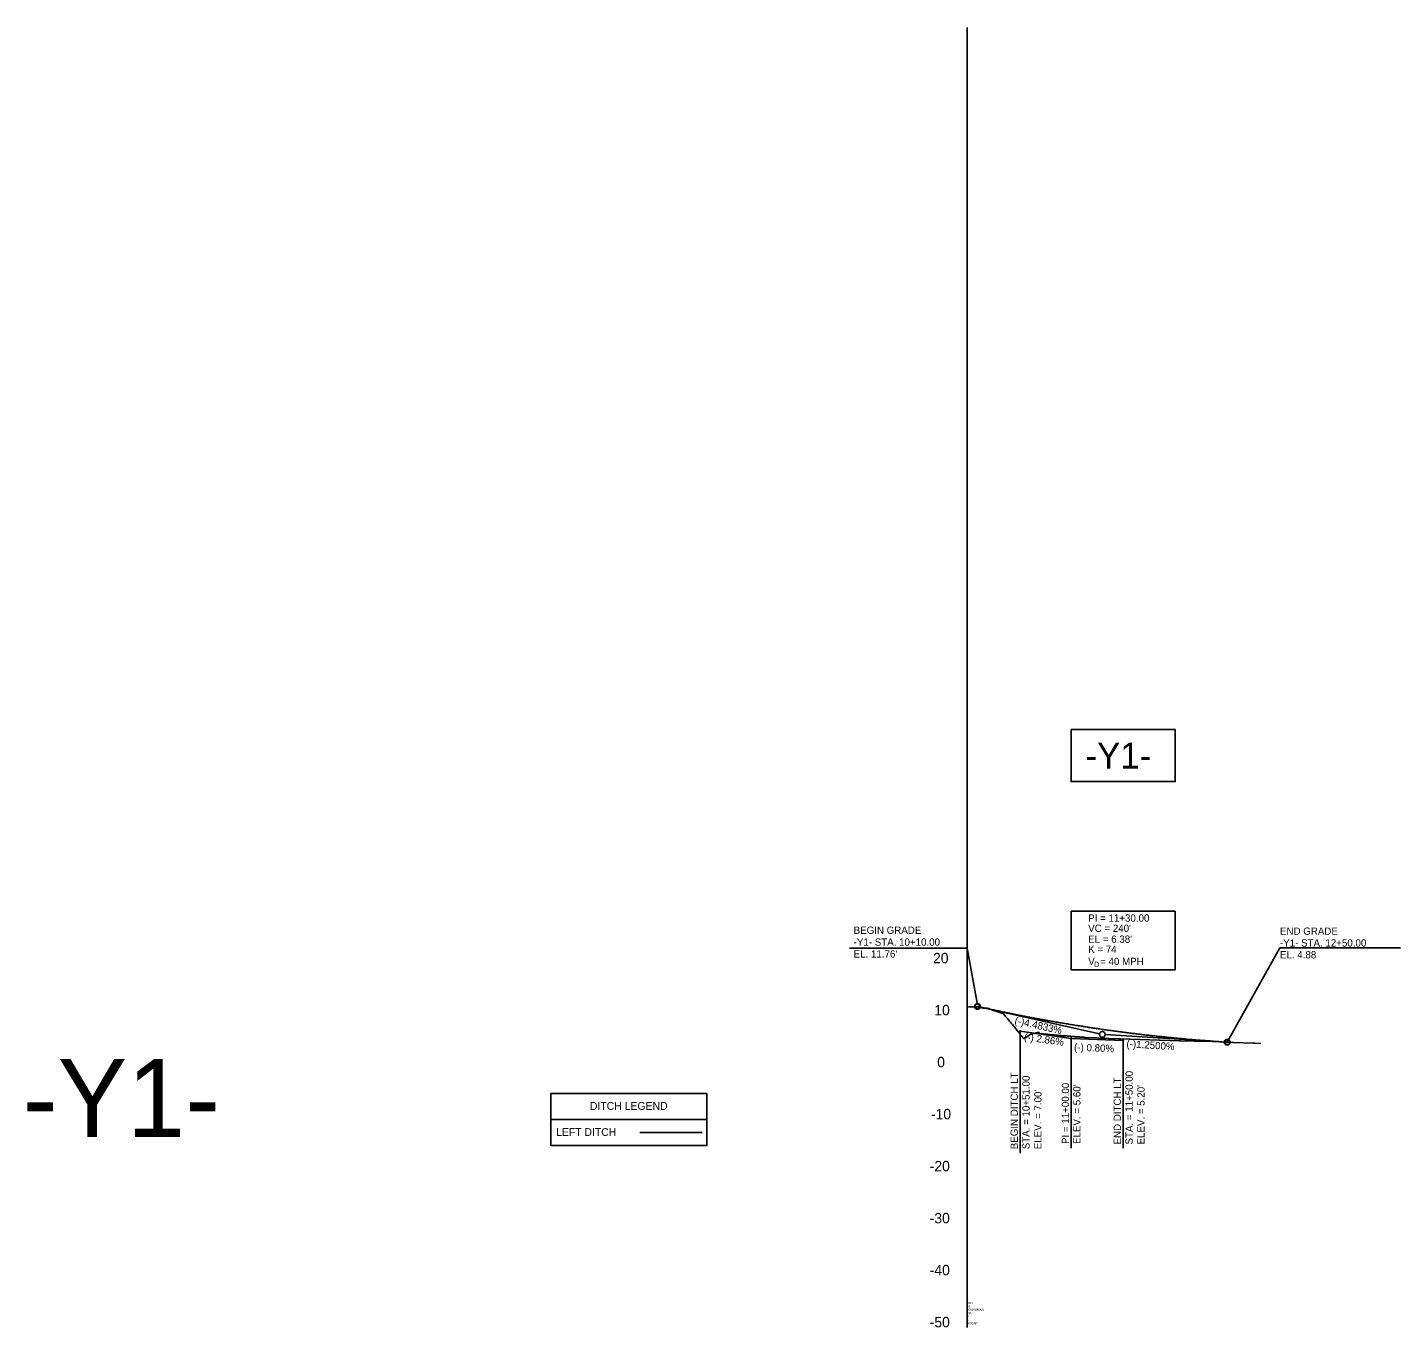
# Model space of a CAD drawing. Extents: x 1626634 to 1638383, y 876896 to 886347.
# Drawn here: x 1637064 to 1638383, y 885097 to 886347 of the extents above; entities that cross this region are included whole.
import ezdxf

# ---------------------------------------------------------------- set-up
doc = ezdxf.new("R2010")
doc.units = 0
for name, color, linetype in [('Exist Profile Cell', 7, 'Continuous'), ('Exist Vertical Profile Ground Line', 7, 'Continuous'), ('Exist Vertical Profile Vertical Axis Label', 7, 'Continuous'), ('Prop Shade Heavy', 7, 'Continuous'), ('Prop Vertical Profile Curve Label', 7, 'Continuous'), ('Prop Vertical Profile Grade', 7, 'Continuous'), ('Prop Vertical Profile Grade Label', 7, 'Continuous'), ('Prop VPI Label', 7, 'Continuous'), ('Scratch_Level_0', 7, 'Continuous'), ('Sheet Block System Information CELL', 7, 'Continuous'), ('Sheet PE Seal Cell', 7, 'Continuous'), ('Stewart Plot Border Xerox6279 and LJ5000', 7, 'Continuous')]:
    doc.layers.add(name, color=color, linetype=linetype)

msp = doc.modelspace()

# ---------------------------------------------------------------- linework, layer by layer
at = {"layer": 'Exist Profile Cell'}
msp.add_line((1637966.7, 885097.1), (1637966.7, 886347.1), dxfattribs=at)
at = {"layer": 'Exist Vertical Profile Ground Line'}
for points in [[(1637966.7, 885405.3), (1637968.7, 885405.4), (1637971.1, 885405.5), (1637972, 885405.5), (1637972.9, 885405.5), (1637973.9, 885405.5), (1637974.8, 885405.5), (1637975.7, 885405.5), (1637976.7, 885405.5), (1637977.2, 885405.5), (1637977.6, 885405.4), (1637978.5, 885405.2), (1637979.4, 885405), (1637980.4, 885404.8), (1637981.3, 885404.6), (1637982.2, 885404.4), (1637983.2, 885404.2), (1637983.5, 885404.1), (1637984.1, 885404.1), (1637985, 885404.1), (1637986, 885404.1), (1637986.9, 885404), (1637987.3, 885404), (1637987.8, 885403.8), (1637988.7, 885403.4), (1637989.7, 885403), (1637990.6, 885402.6), (1637991.7, 885402.1), (1637992.5, 885401.9), (1637993.4, 885401.6), (1637994.3, 885401.3), (1637995.3, 885401), (1637996.2, 885400.7), (1637997.1, 885400.5), (1637998.1, 885400.2), (1637999, 885399.9), (1638000.1, 885399.6), (1638000.8, 885399.5), (1638001.2, 885399.4), (1638001.8, 885398.8), (1638002.7, 885397.6), (1638003.6, 885396.4), (1638004.6, 885395.3), (1638005.5, 885394.2), (1638006.4, 885393), (1638007.4, 885391.9), (1638008.3, 885390.8), (1638009.2, 885389.8), (1638010.2, 885388.7), (1638011.1, 885387.6), (1638011.5, 885387.1), (1638012, 885386.5), (1638012.9, 885385.2), (1638013.9, 885384), (1638014.8, 885382.8), (1638015.7, 885381.6), (1638016.7, 885380.4), (1638017.6, 885379.2), (1638018.5, 885378.1), (1638019.5, 885376.9), (1638020.4, 885375.8), (1638021, 885375.1), (1638021.3, 885375.2), (1638022.2, 885375.6), (1638022.7, 885375.7), (1638023.2, 885376.1), (1638024.1, 885376.7), (1638025, 885377.4), (1638026, 885378), (1638026.9, 885378.7), (1638028.1, 885379.2), (1638028.8, 885379.4), (1638029.7, 885379.6), (1638030.6, 885379.8), (1638031.6, 885380), (1638032.5, 885380.3), (1638032.9, 885380.4), (1638033.4, 885380.5), (1638034.3, 885380.8), (1638035.4, 885381.1), (1638036.2, 885379.8), (1638037.1, 885379.7), (1638038.1, 885379.7), (1638039, 885379.6), (1638039.9, 885379.5), (1638040.9, 885379.4), (1638041.8, 885379.3), (1638042.7, 885379.2), (1638043.7, 885379.1), (1638044.6, 885379), (1638045.5, 885378.9), (1638046.4, 885378.8), (1638047.4, 885378.7), (1638048.3, 885378.7), (1638049.2, 885378.6), (1638050.2, 885378.5), (1638051.1, 885378.4), (1638052, 885378.3), (1638053, 885378.2), (1638053.9, 885378.2), (1638054.8, 885378.1)], [(1638054.8, 885378.1), (1638055.7, 885378), (1638056.7, 885377.9), (1638057.6, 885377.8), (1638058.5, 885377.8), (1638059.5, 885377.7), (1638060.4, 885377.6), (1638061.3, 885377.5), (1638062.3, 885377.5), (1638063.2, 885377.4), (1638064.1, 885377.3), (1638065.1, 885377.2), (1638066, 885377.2), (1638066.9, 885377.1), (1638067.8, 885377), (1638068.8, 885377), (1638069.7, 885376.9), (1638070.6, 885376.8), (1638070.9, 885376.8), (1638071.6, 885376.8), (1638072.1, 885376.7), (1638072.5, 885376.7), (1638073.4, 885376.6), (1638074.4, 885376.6), (1638075.3, 885376.5), (1638076.2, 885376.4), (1638077.1, 885376.4), (1638078.1, 885376.3), (1638079, 885376.3), (1638079.9, 885376.2), (1638080.9, 885376.2), (1638091.8, 885375.6), (1638093.4, 885375.5), (1638112.5, 885374.8), (1638114.3, 885374.7), (1638133.2, 885374.1), (1638151.2, 885373.5), (1638152.3, 885373.5), (1638170.5, 885372.9), (1638171.3, 885372.8), (1638171.8, 885372.8), (1638184.9, 885372.5), (1638185.4, 885372.5), (1638202.4, 885372.1), (1638203, 885372.1), (1638222.1, 885371.3), (1638222.8, 885371.3), (1638241.8, 885370.6), (1638243.3, 885370.5), (1638248.9, 885370.3)]]:
    msp.add_lwpolyline(points, dxfattribs=at)
at = {"layer": 'Prop Shade Heavy'}
for points in [[(1637566.7, 885322.1), (1637716.7, 885322.1), (1637716.7, 885297.1), (1637566.7, 885297.1)], [(1637566.7, 885297.1), (1637716.7, 885297.1), (1637716.7, 885272.1), (1637566.7, 885272.1)]]:
    msp.add_lwpolyline(points, close=True, dxfattribs=at)
at = {"layer": 'Prop Vertical Profile Curve Label'}
for centre in [(1637976.7, 885405.9), (1638216.7, 885371.5)]:
    msp.add_circle(centre, 2.25, dxfattribs=at)
at = {"layer": 'Prop Vertical Profile Grade'}
msp.add_spline([(1637976.7, 885405.9), (1637981.5, 885404.9), (1637986.3, 885403.8), (1637991.1, 885402.8), (1637995.9, 885401.8), (1638000.7, 885400.8), (1638005.5, 885399.8), (1638010.3, 885398.8), (1638015.1, 885397.8), (1638019.9, 885396.9), (1638024.7, 885396), (1638029.5, 885395), (1638034.3, 885394.1), (1638039.1, 885393.3), (1638043.9, 885392.4), (1638048.7, 885391.5), (1638053.5, 885390.7), (1638058.3, 885389.9), (1638063.1, 885389.1), (1638067.9, 885388.3), (1638072.7, 885387.5), (1638077.5, 885386.8), (1638082.3, 885386), (1638087.1, 885385.3), (1638091.9, 885384.6), (1638096.7, 885383.9), (1638101.5, 885383.2), (1638106.3, 885382.5), (1638111.1, 885381.9), (1638115.9, 885381.3), (1638120.7, 885380.6), (1638125.5, 885380), (1638130.3, 885379.5), (1638135.1, 885378.9), (1638139.9, 885378.3), (1638144.7, 885377.8), (1638149.5, 885377.3), (1638154.3, 885376.8), (1638159.1, 885376.3), (1638163.9, 885375.8), (1638168.7, 885375.3), (1638173.5, 885374.9), (1638178.3, 885374.4), (1638183.1, 885374), (1638187.9, 885373.6), (1638192.7, 885373.2), (1638197.5, 885372.9), (1638202.3, 885372.5), (1638207.1, 885372.2), (1638211.9, 885371.8), (1638216.7, 885371.5)], degree=3, dxfattribs=at)
at = {"layer": 'Prop VPI Label'}
for p, q in [((1637966.9, 885461.8), (1637853.8, 885461.8)), ((1637976.7, 885407.6), (1637966.9, 885461.8)), ((1638216.7, 885371.5), (1638267.4, 885462.2)), ((1638383.3, 885462.2), (1638267.4, 885462.2)), ((1637976.7, 885405.9), (1638094, 885379.6)), ((1638216.7, 885371.5), (1638099.4, 885378.9))]:
    msp.add_line(p, q, dxfattribs=at)
for points in [[(1638066.7, 885672.1), (1638166.7, 885672.1), (1638166.7, 885622.1), (1638066.7, 885622.1)], [(1638066.7, 885672.1), (1638166.7, 885672.1), (1638166.7, 885622.1), (1638066.7, 885622.1)], [(1638066.7, 885672.1), (1638166.7, 885672.1), (1638166.7, 885622.1), (1638066.7, 885622.1)], [(1638066.7, 885672.1), (1638166.7, 885672.1), (1638166.7, 885622.1), (1638066.7, 885622.1)], [(1638066.6, 885497.4), (1638166.6, 885497.4), (1638166.6, 885441.2), (1638066.6, 885441.2)], [(1638066.6, 885497.4), (1638166.6, 885497.4), (1638166.6, 885441.2), (1638066.6, 885441.2)]]:
    msp.add_lwpolyline(points, close=True, dxfattribs=at)
for centre in [(1637976.7, 885405.9), (1637976.7, 885405.9), (1638096.7, 885379), (1638216.7, 885371.5), (1638216.7, 885371.5), (1638216.7, 885371.5)]:
    msp.add_circle(centre, 2.75, dxfattribs=at)
at = {"layer": 'Scratch_Level_0'}
for p, q in [((1638017.7, 885382.1), (1638017.7, 885264.7)), ((1638066.7, 885375.1), (1638066.7, 885269.7)), ((1638116.7, 885373.1), (1638116.7, 885269.7))]:
    msp.add_line(p, q, dxfattribs=at)
for centre in [(1638017.7, 885382.1), (1638066.7, 885375.1), (1638116.7, 885373.1)]:
    msp.add_circle(centre, 0.5, dxfattribs=at)
at = {"layer": 'Sheet PE Seal Cell'}
msp.add_line((1637652.2, 885284.8), (1637712.2, 885284.8), dxfattribs=at)
at = {"layer": 'Stewart Plot Border Xerox6279 and LJ5000'}
msp.add_lwpolyline([(1638017.7, 885382.1), (1638066.7, 885375.1), (1638116.7, 885373.1)], dxfattribs=at)

# ---------------------------------------------------------------- texts
at = {"layer": 'Exist Profile Cell'}
for s, p in [('Y1', (1637966.7, 885116.6)), ('-50', (1637966.7, 885110.1)), ('RDY', (1637966.7, 885119.9)), ('1000.000000', (1637966.7, 885113.4)), ('5', (1637966.7, 885106.9)), ('1', (1637966.7, 885103.6)), ('NOGAP', (1637966.7, 885100.4))]:
    msp.add_text(s, height=2, dxfattribs=at).set_placement(p)
at = {"layer": 'Exist Vertical Profile Vertical Axis Label'}
for s, p in [('20', (1637934, 885447.4)), ('10', (1637935.2, 885397.4)), ('0', (1637938, 885347.4)), ('-10', (1637932, 885297.4)), ('-20', (1637930.8, 885247.4)), ('-30', (1637930.8, 885197.4)), ('-40', (1637930.8, 885147.4)), ('-50', (1637930.8, 885097.4))]:
    msp.add_text(s, height=10, dxfattribs=at).set_placement(p)
at = {"layer": 'Prop Vertical Profile Curve Label'}
for s, height, p in [('-Y1-', 25, (1638080.5, 885634.6)), ("VC = 240'", 7, (1638083.1, 885477.6)), ('K = 74', 7, (1638083.1, 885457.4)), ('-Y1-', 75, (1637059.2, 885280.4))]:
    msp.add_text(s, height=height, dxfattribs=at).set_placement(p)
for s, height, p in [('V  = 40 MPH', 7, (1638083.1, 885445.7)), ('D', 5.25, (1638088.6, 885443.7))]:
    msp.add_text(s, height=height, rotation=360, dxfattribs=at).set_placement(p)
at = {"layer": 'Prop Vertical Profile Grade Label'}
for s, rotation, p in [('(-)4.4833%', 347.3653, (1638011.9, 885389.3)), ('(-)1.2500%', 356.4237, (1638119.7, 885366.7))]:
    msp.add_text(s, height=7, rotation=rotation, dxfattribs=at).set_placement(p)
at = {"layer": 'Prop VPI Label'}
for s, p in [('PI = 11+30.00', (1638083.1, 885487.4)), ('BEGIN GRADE', (1637857.7, 885475.7)), ('END GRADE', (1638267.4, 885474.8)), ('-Y1- STA. 10+10.00', (1637857.7, 885464.3)), ("EL = 6.38'", (1638083.1, 885467.1)), ('-Y1- STA. 12+50.00', (1638267.4, 885463.5)), ("EL. 11.76'", (1637857.7, 885452.9)), ('EL. 4.88', (1638267.4, 885452.1))]:
    msp.add_text(s, height=7, dxfattribs=at).set_placement(p)
at = {"layer": 'Scratch_Level_0'}
for s, p in [('BEGIN DITCH LT', (1638015.5, 885268.6)), ('STA. = 10+51.00', (1638026.8, 885268.6)), ('END DITCH LT ', (1638114.6, 885273.2)), ('STA. = 11+50.00', (1638125.9, 885273.2)), ("ELEV. = 7.00'", (1638038.2, 885268.6)), ('PI = 11+00.00', (1638064.7, 885273.7)), ("ELEV. = 5.60'", (1638075.7, 885273.7)), ("ELEV. = 5.20'", (1638137.3, 885273.2))]:
    msp.add_text(s, height=7, rotation=90, dxfattribs=at).set_placement(p)
at = {"layer": 'Sheet Block System Information CELL'}
for s, rotation, p in [('(-) 2.86%', 351.7377, (1638021.1, 885373.5)), ('(-) 0.80%', 357.7094, (1638069.4, 885363.4))]:
    msp.add_text(s, height=7, rotation=rotation, dxfattribs=at).set_placement(p)
at = {"layer": 'Sheet PE Seal Cell'}
for s, height, p in [('DITCH LEGEND', 7.5, (1637604.2, 885306.5)), ('LEFT DITCH', 7.49, (1637571.7, 885281.4))]:
    msp.add_text(s, height=height, dxfattribs=at).set_placement(p)

doc.saveas('drawing.dxf')
